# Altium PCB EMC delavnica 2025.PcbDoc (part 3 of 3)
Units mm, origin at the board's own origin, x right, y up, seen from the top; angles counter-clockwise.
Board outline 146.35 x 55.01 mm, 2 copper layers (Top Layer, Bottom Layer), stack 1.671 mm thick; 5 components, 5 nets, 32 pads, 0 vias.
Unrouted connection lines stored in the file: 7.
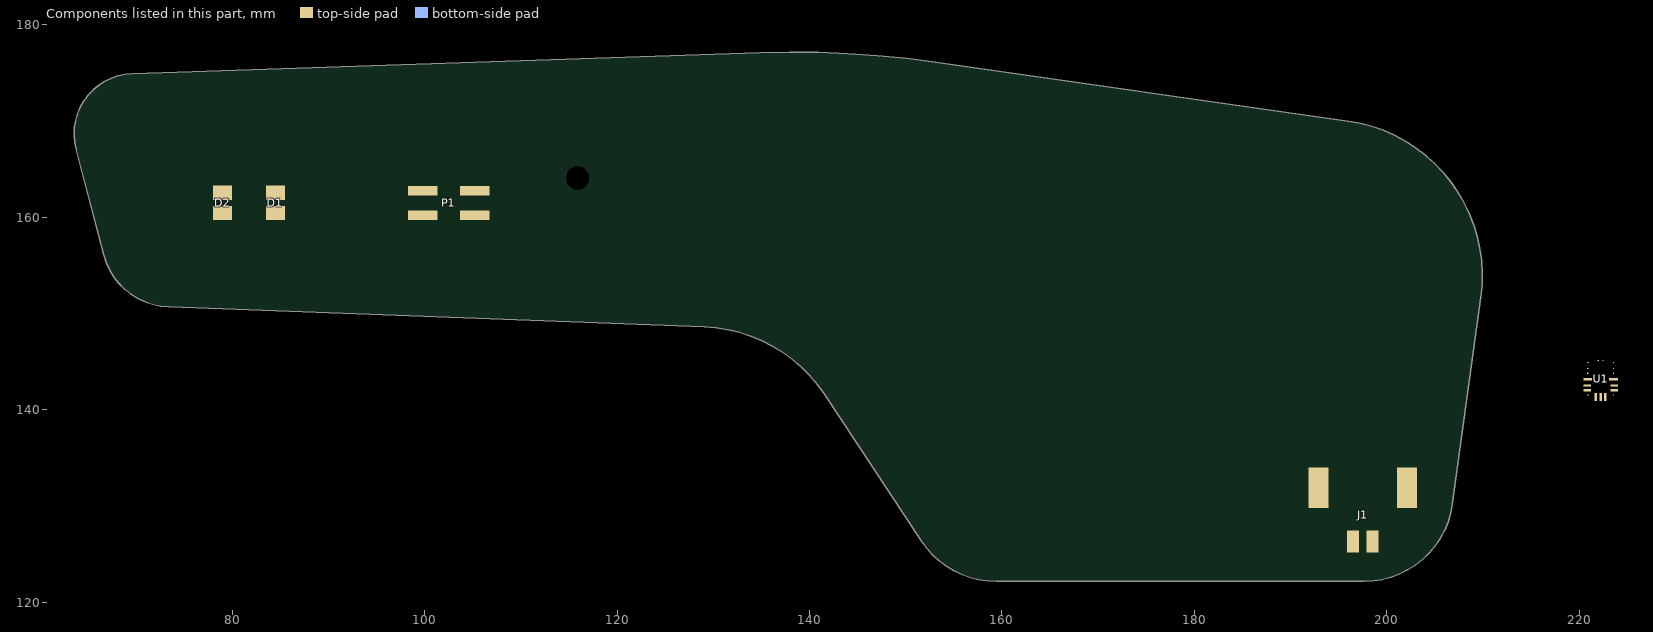
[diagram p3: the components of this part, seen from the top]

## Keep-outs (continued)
Top Layer: (continued)
  lines w0.203: 197.064,156.203 ccw(c197.307,156.588) 197.064,156.203 ; 197.064,156.203 ccw(c197.308,156.587) 197.064,156.203 ; 197.064,156.203 ccw(c197.308,156.587) 197.064,156.203 ; 197.064,156.203 ccw(c197.552,156.972) 197.064,156.203 ; 197.064,156.203 197.064,156.203 ; 197.064,156.203 ccw(c197.307,156.588) 197.064,156.203 ; 197.064,156.203 ccw(c197.308,156.587) 197.065,156.203 ; 197.064,156.203 ccw(c197.308,156.587) 197.064,156.203 ; 197.065,156.203 ccw(c197.552,156.972) 197.224,156.122 ; 197.064,156.203 ccw(c197.552,156.972) 197.224,156.122 ; 197.128,159.92 ccw(c197.499,159.088) 197.128,159.92 ; 197.128,159.92 cw(c197.499,159.088) 197.129,159.92 ; 197.128,159.92 cw(c197.314,159.504) 197.129,159.92 ; 197.128,159.92 cw(c197.313,159.504) 197.129,159.92 ; 197.128,159.92 197.129,159.92 ; 197.129,159.921 ccw(c197.313,159.504) 197.129,159.92 ; 197.129,159.921 ccw(c197.314,159.504) 197.129,159.92 ; 197.129,159.92 ccw(c197.499,159.088) 197.129,159.92 ; 197.129,159.921 ccw(c197.314,159.504) 197.129,159.92 ; 197.13,159.921 ccw(c197.314,159.504) 197.129,159.921 ; 197.13,159.921 ccw(c197.499,159.088) 197.129,159.92 ; 197.129,159.921 197.342,160.015 ; 197.129,159.92 197.129,159.921 ; 197.224,156.122 197.443,156.038 ; 197.342,160.015 ccw(c197.528,159.599) 197.341,160.015 ; 197.342,160.015 cw(c197.528,159.599) 197.342,160.015 ; 197.341,160.015 ccw(c197.713,159.183) 197.341,160.015 ; 197.342,160.015 cw(c197.527,159.599) 197.342,160.015 ; 197.341,160.015 cw(c197.713,159.183) 197.342,160.015 ; 197.341,160.015 197.342,160.015 ; 197.342,160.015 197.342,160.015 ; 197.342,160.015 197.342,160.015 ; 197.342,160.015 197.342,160.015 ; 197.342,160.015 cw(c197.528,159.599) 197.343,160.016 cw(c197.713,159.183) 197.513,160.072 ; 197.342,160.015 cw(c197.713,159.183) 197.512,160.072 ; 197.443,156.038 ccw(c197.771,156.888) 197.615,155.99 ; 197.443,156.038 ccw(c197.771,156.888) 197.615,155.99 ; 197.513,160.072 ccw(c197.713,159.183) 197.513,160.072 ; 197.513,160.072 ccw(c197.613,159.628) 197.513,160.072 ; 197.513,160.072 ccw(c197.613,159.628) 197.513,160.072 ; 197.513,160.072 cw(c197.713,159.183) 197.514,160.072 ; 197.513,160.072 cw(c197.614,159.628) 197.514,160.072 ; 197.513,160.072 ccw(c197.613,159.628) 197.512,160.072 ; 197.513,160.072 ccw(c197.614,159.628) 197.513,160.072 ; 197.513,160.072 ccw(c197.613,159.628) 197.513,160.072 ; 197.513,160.072 ccw(c197.614,159.628) 197.513,160.072 ; 197.513,160.072 197.514,160.072 ; 197.513,160.072 197.513,160.072 ; 197.513,160.072 197.513,160.072 ; 197.514,160.072 197.74,160.123 ; 197.615,155.99 ccw(c197.771,156.888) 197.615,155.99 ; 197.615,155.99 ccw(c197.694,156.439) 197.615,155.99 ; 197.615,155.99 ccw(c197.771,156.888) 197.615,155.99 ; 197.615,155.99 197.615,155.99 ; 197.615,155.99 ccw(c197.693,156.439) 197.616,155.99 ; 197.615,155.99 ccw(c197.694,156.439) 197.616,155.99 ; 197.615,155.99 ccw(c197.694,156.439) 197.617,155.99 ; 197.615,155.99 ccw(c197.771,156.888) 197.615,155.99 ; 197.616,155.99 ccw(c197.771,156.888) 197.617,155.99 ; 197.615,155.99 ccw(c197.771,156.888) 197.616,155.99 ; 197.616,155.99 197.617,155.99 ; 197.616,155.99 197.616,155.99 ; 197.617,155.99 ccw(c197.694,156.439) 197.617,155.99 ; 197.617,155.99 ccw(c197.694,156.439) 197.617,155.99 ; 197.617,155.99 197.846,155.95 ; 197.74,160.123 cw(c197.943,159.235) 197.741,160.124 ; 197.74,160.123 cw(c197.841,159.679) 197.741,160.124 ; 197.74,160.123 197.74,160.123 ; 197.74,160.123 197.741,160.124 ; 197.741,160.124 ccw(c197.842,159.679) 197.741,160.124 ; 197.742,160.124 ccw(c197.842,159.679) 197.741,160.124 ; 197.741,160.124 ccw(c197.841,159.679) 197.741,160.124 ; 197.742,160.124 ccw(c197.943,159.235) 197.741,160.124 ; 197.742,160.124 ccw(c197.841,159.679) 197.741,160.124 ; 197.742,160.124 cw(c197.943,159.235) 197.919,160.146 ; 197.742,160.124 cw(c197.943,159.235) 197.919,160.146 ; 197.741,160.124 197.742,160.124 ; 197.741,160.124 197.741,160.124 ; 197.846,155.95 ccw(c197.924,156.399) 197.846,155.95 ; 197.846,155.95 ccw(c198.003,156.848) 197.847,155.95 ; 197.846,155.95 ccw(c197.924,156.399) 197.846,155.95 ; 197.846,155.95 ccw(c198.003,156.848) 197.846,155.95 ; 197.846,155.95 ccw(c197.925,156.399) 197.847,155.95 ; 197.846,155.95 ccw(c197.925,156.399) 197.846,155.95 ; 197.846,155.95 197.846,155.95 ; 197.846,155.95 197.846,155.95 ; 197.846,155.95 197.847,155.95 ; 197.847,155.95 ccw(c198.003,156.848) 197.937,155.939 ; 197.847,155.95 ccw(c197.925,156.399) 197.847,155.95 ; 197.847,155.95 ccw(c198.003,156.848) 197.937,155.939 ; 197.846,155.95 ccw(c197.924,156.399) 197.847,155.95 ; 197.92,160.146 ccw(c197.931,159.691) 197.919,160.146 ; 197.92,160.146 ccw(c197.931,159.69) 197.919,160.146 ; 197.919,160.146 cw(c197.943,159.235) 197.92,160.146 ; 197.92,160.146 cw(c197.931,159.69) 197.92,160.146 ; 197.919,160.146 ccw(c197.931,159.69) 197.919,160.146 ; 197.92,160.146 197.92,160.146 ; 197.92,160.146 197.92,160.146 ; 197.919,160.146 197.92,160.146 ; 197.92,160.146 197.92,160.146 ; 197.92,160.146 197.92,160.146 ; 197.92,160.146 ccw(c197.943,159.235) 197.92,160.146 ; 197.92,160.146 ccw(c197.931,159.691) 197.92,160.146 ; 197.92,160.146 198.152,160.152 ; 197.937,155.939 198.734,155.881 ; 198.152,160.152 ccw(c198.165,159.697) 198.152,160.152 ; 198.152,160.152 cw(c198.165,159.697) 198.153,160.152 ; 198.152,160.152 cw(c198.178,159.241) 198.153,160.152 ; 198.152,160.152 198.153,160.152 ; 198.153,160.152 cw(c198.166,159.697) 198.154,160.152 ; 198.153,160.152 cw(c198.178,159.241) 198.154,160.152 ; 198.153,160.152 ccw(c198.165,159.697) 198.153,160.152 ; 198.153,160.152 cw(c198.165,159.697) 198.154,160.152 ; 198.153,160.152 ccw(c198.166,159.697) 198.153,160.152 ; 198.153,160.152 ccw(c198.178,159.241) 198.153,160.152 ; 198.153,160.152 198.153,160.152 ; 198.153,160.152 198.154,160.152 ; 198.154,160.152 cw(c198.178,159.241) 198.244,160.15 ; 198.154,160.152 ccw(c198.178,159.241) 198.154,160.152 ; 198.154,160.152 cw(c198.178,159.241) 198.244,160.15 ; 198.244,160.15 199.042,160.092 ; 198.734,155.881 ccw(c198.801,156.789) 198.825,155.878 ; 198.734,155.881 ccw(c198.801,156.789) 198.825,155.878 ; 198.825,155.878 ccw(c198.814,156.334) 198.826,155.878 ; 198.825,155.878 ccw(c198.814,156.334) 198.825,155.878 ; 198.825,155.878 ccw(c198.813,156.334) 198.826,155.878 ; 198.825,155.878 ccw(c198.813,156.334) 198.825,155.878 ; 198.825,155.878 ccw(c198.801,156.789) 198.826,155.878 ; 198.825,155.878 198.826,155.878 ; 198.826,155.878 ccw(c198.814,156.334) 198.827,155.878 ; 198.826,155.878 ccw(c198.801,156.789) 198.827,155.878 ; 198.826,155.878 198.827,155.878 ; 198.826,155.878 198.826,155.878 ; 198.827,155.878 199.058,155.885 ; 198.827,155.878 198.827,155.878 ; 199.042,160.092 cw(c198.976,159.183) 199.131,160.081 ; 199.042,160.092 cw(c198.976,159.183) 199.131,160.081 ; 199.058,155.885 ccw(c199.047,156.34) 199.059,155.885 ; 199.058,155.885 ccw(c199.036,156.795) 199.059,155.885 ; 199.058,155.885 ccw(c199.036,156.795) 199.058,155.885 ; 199.058,155.885 199.059,155.885 ; 199.058,155.885 199.058,155.885 ; 199.059,155.885 ccw(c199.036,156.795) 199.06,155.885 ; 199.059,155.885 ccw(c199.047,156.34) 199.06,155.885 ; 199.059,155.885 ccw(c199.048,156.34) 199.06,155.885 ; 199.059,155.885 ccw(c199.047,156.34) 199.059,155.885 ; 199.059,155.885 ccw(c199.048,156.34) 199.059,155.885 ; 199.059,155.885 ccw(c199.047,156.34) 199.059,155.885 ; 199.059,155.885 199.06,155.885 ; 199.059,155.885 199.059,155.885 ; 199.06,155.885 ccw(c199.036,156.795) 199.237,155.907 ; 199.06,155.885 ccw(c199.036,156.795) 199.237,155.907 ; 199.06,155.885 ccw(c199.036,156.795) 199.06,155.885 ; 199.131,160.081 199.363,160.04 ; 199.237,155.907 199.466,155.959 ; 199.363,160.04 cw(c199.207,159.143) 199.535,159.993 ; 199.363,160.04 cw(c199.207,159.143) 199.535,159.993 ; 199.466,155.959 ccw(c199.265,156.847) 199.635,156.015 ; 199.466,155.959 ccw(c199.265,156.847) 199.635,156.015 ; 199.535,159.993 cw(c199.207,159.143) 199.536,159.993 ; 199.535,159.993 ccw(c199.207,159.143) 199.535,159.993 ; 199.535,159.993 cw(c199.372,159.567) 199.536,159.993 ; 199.535,159.993 cw(c199.371,159.568) 199.536,159.993 ; 199.535,159.993 199.536,159.993 ; 199.537,159.992 ccw(c199.207,159.143) 199.536,159.993 ; 199.536,159.992 ccw(c199.372,159.567) 199.536,159.993 ; 199.537,159.992 cw(c199.207,159.143) 199.537,159.992 ccw(c199.372,159.567) 199.537,159.992 ; 199.537,159.992 ccw(c199.372,159.567) 199.536,159.993 ; 199.536,159.992 199.537,159.992 ; 199.537,159.992 199.753,159.909 ; 199.537,159.992 199.537,159.992 ; 199.636,156.015 ccw(c199.451,156.431) 199.636,156.015 ; 199.635,156.015 ccw(c199.265,156.847) 199.636,156.015 ; 199.636,156.015 ccw(c199.451,156.431) 199.636,156.015 ; 199.636,156.015 ccw(c199.45,156.431) 199.636,156.015 ; 199.635,156.015 ccw(c199.451,156.431) 199.636,156.015 ; 199.636,156.015 ccw(c199.265,156.847) 199.636,156.015 ; 199.635,156.015 ccw(c199.265,156.847) 199.636,156.015 ; 199.635,156.015 199.636,156.015 ; 199.636,156.015 ccw(c199.265,156.847) 199.637,156.015 ; 199.636,156.015 ccw(c199.451,156.431) 199.637,156.015 ; 199.636,156.015 199.85,156.11 ; 199.753,159.909 ccw(c199.589,159.484) 199.753,159.909 ; 199.753,159.909 cw(c199.59,159.483) 199.754,159.908 ; 199.753,159.909 cw(c199.589,159.484) 199.754,159.908 ; 199.753,159.909 ccw(c199.426,159.058) 199.753,159.909 ; 199.753,159.909 cw(c199.426,159.058) 199.754,159.908 ; 199.753,159.909 199.754,159.908 ; 199.753,159.909 199.753,159.909 ; 199.753,159.909 199.753,159.909 ; 199.754,159.908 ccw(c199.59,159.483) 199.754,159.908 ; 199.754,159.908 cw(c199.426,159.058) 199.914,159.828 ; 199.754,159.908 cw(c199.426,159.058) 199.914,159.828 ; 199.85,156.11 ccw(c199.665,156.526) 199.85,156.11 ; 199.85,156.11 ccw(c199.48,156.943) 199.85,156.11 ; 199.849,156.11 ccw(c199.665,156.526) 199.85,156.11 ; 199.849,156.11 ccw(c199.48,156.943) 199.85,156.11 ; 199.85,156.11 ccw(c199.665,156.526) 199.851,156.111 ; 199.85,156.11 ccw(c199.665,156.526) 199.85,156.11 ; 199.85,156.11 ccw(c199.665,156.527) 199.85,156.11 ccw(c199.48,156.943) 199.851,156.111 ; 199.85,156.11 ccw(c199.665,156.527) 199.85,156.11 ; 199.85,156.11 ccw(c199.48,156.943) 199.851,156.111 ; 199.85,156.11 199.851,156.111 ; 199.851,156.111 ccw(c199.48,156.943) 200.006,156.199 ; 199.851,156.111 ccw(c199.48,156.943) 200.006,156.199 ; 199.914,159.828 200.113,159.702 ; 200.006,156.199 200.198,156.334 ; 200.113,159.702 cw(c199.625,158.932) 200.253,159.592 ; 200.113,159.702 cw(c199.625,158.932) 200.253,159.592 ; 200.198,156.334 ccw(c199.672,157.079) 200.332,156.451 ; 200.198,156.334 ccw(c199.672,157.079) 200.332,156.451 ; 200.253,159.592 200.424,159.43 ; 200.332,156.451 ccw(c199.672,157.079) 200.333,156.451 ; 200.332,156.451 ccw(c200.003,156.766) 200.333,156.452 ; 200.333,156.451 ccw(c200.002,156.765) 200.333,156.452 ; 200.332,156.451 ccw(c199.672,157.079) 200.333,156.452 ; 200.332,156.451 200.333,156.452 ; 200.333,156.452 ccw(c200.003,156.766) 200.333,156.452 ; 200.333,156.452 ccw(c200.003,156.766) 200.334,156.453 ; 200.333,156.452 ccw(c199.672,157.079) 200.334,156.452 ; 200.333,156.452 200.334,156.452 ; 200.334,156.452 ccw(c199.672,157.079) 200.334,156.453 ; 200.334,156.453 200.493,156.62 ; 200.334,156.452 200.334,156.453 ; 200.424,159.43 cw(c199.795,158.77) 200.54,159.295 ; 200.424,159.43 cw(c199.795,158.77) 200.54,159.295 ; 200.493,156.62 ccw(c199.834,157.249) 200.493,156.62 ; 200.494,156.621 ccw(c200.163,156.934) 200.494,156.621 ; 200.493,156.62 ccw(c200.163,156.934) 200.494,156.621 ; 200.493,156.62 ccw(c199.834,157.249) 200.494,156.621 ; 200.493,156.62 200.494,156.621 ; 200.493,156.62 200.493,156.62 ; 200.494,156.621 ccw(c200.163,156.934) 200.494,156.621 ; 200.494,156.621 ccw(c200.164,156.935) 200.494,156.621 ; 200.494,156.621 ccw(c199.834,157.249) 200.495,156.622 ; 200.494,156.621 200.495,156.622 ; 200.494,156.621 ccw(c200.164,156.935) 200.495,156.621 ; 200.495,156.622 ccw(c199.834,157.249) 200.604,156.762 ; 200.495,156.622 ccw(c199.834,157.249) 200.604,156.762 ; 200.495,156.621 ccw(c199.834,157.249) 200.495,156.622 ; 200.494,156.621 ccw(c200.163,156.934) 200.495,156.622 ; 200.541,159.295 ccw(c200.168,159.032) 200.54,159.295 ; 200.54,159.295 ccw(c199.795,158.77) 200.54,159.295 ; 200.541,159.295 ccw(c200.168,159.032) 200.541,159.295 ; 200.541,159.295 ccw(c200.168,159.033) 200.54,159.295 ; 200.541,159.294 ccw(c200.168,159.032) 200.541,159.295 ; 200.541,159.295 ccw(c199.795,158.77) 200.54,159.295 ; 200.541,159.294 ccw(c199.795,158.77) 200.541,159.295 ; 200.541,159.294 ccw(c199.795,158.77) 200.541,159.294 ; 200.541,159.294 200.541,159.294 ; 200.54,159.295 200.541,159.295 ; 200.541,159.294 200.675,159.104 ; 200.541,159.295 200.541,159.295 ; 200.541,159.295 200.541,159.294 ; 200.604,156.762 200.73,156.961 ; 200.676,159.103 ccw(c200.303,158.841) 200.675,159.104 ; 200.676,159.103 cw(c200.303,158.841) 200.676,159.103 ; 200.675,159.103 ccw(c199.931,158.578) 200.675,159.104 ; 200.676,159.103 ccw(c199.931,158.578) 200.675,159.103 ; 200.676,159.103 ccw(c200.303,158.841) 200.675,159.104 ; 200.676,159.103 cw(c199.931,158.578) 200.676,159.103 ; 200.676,159.103 ccw(c200.303,158.841) 200.676,159.103 ; 200.676,159.103 ccw(c200.303,158.841) 200.675,159.104 ; 200.676,159.103 cw(c199.931,158.578) 200.676,159.103 ; 200.675,159.104 200.675,159.104 ; 200.675,159.104 200.675,159.103 ; 200.676,159.103 200.676,159.103 ; 200.676,159.103 cw(c199.931,158.578) 200.764,158.948 ; 200.676,159.103 cw(c199.931,158.578) 200.764,158.948 ; 200.73,156.961 ccw(c199.959,157.448) 200.81,157.121 ; 200.73,156.961 ccw(c199.959,157.448) 200.81,157.121 ; 200.764,158.948 200.859,158.733 ; 200.81,157.121 ccw(c200.385,157.285) 200.81,157.121 ; 200.81,157.121 ccw(c199.959,157.448) 200.81,157.121 ; 200.81,157.121 ccw(c200.385,157.284) 200.81,157.121 ; 200.81,157.121 ccw(c200.385,157.284) 200.81,157.121 ; 200.81,157.121 200.81,157.121 ; 200.81,157.121 ccw(c200.385,157.284) 200.81,157.121 ; 200.81,157.121 ccw(c199.959,157.448) 200.81,157.122 ; 200.81,157.121 ccw(c199.959,157.448) 200.81,157.121 ; 200.81,157.121 200.894,157.339 ; 200.859,158.733 cw(c200.026,158.363) 200.915,158.563 ; 200.859,158.733 cw(c200.026,158.363) 200.915,158.563 ; 200.894,157.339 ccw(c200.469,157.503) 200.894,157.34 ; 200.894,157.339 ccw(c200.044,157.667) 200.942,157.512 ; 200.894,157.339 ccw(c200.469,157.504) 200.894,157.34 ccw(c200.044,157.667) 200.942,157.512 ; 200.894,157.339 ccw(c200.044,157.667) 200.894,157.339 ; 200.894,157.339 ccw(c200.469,157.504) 200.894,157.339 ; 200.894,157.339 ccw(c200.044,157.667) 200.894,157.339 ; 200.894,157.339 ccw(c200.469,157.504) 200.894,157.339 ; 200.894,157.339 ccw(c200.044,157.667) 200.894,157.339 ; 200.894,157.339 200.894,157.339 ; 200.894,157.339 200.894,157.339 ; 200.915,158.563 200.967,158.334 ; 200.942,157.512 200.982,157.744 ; 200.967,158.334 cw(c200.078,158.134) 200.989,158.157 ; 200.967,158.334 cw(c200.078,158.134) 200.989,158.157 ; 200.982,157.744 ccw(c200.084,157.899) 200.995,157.899 ; 200.982,157.744 ccw(c200.084,157.899) 200.995,157.899 ; 200.989,158.157 200.995,157.922 ; 200.995,157.899 ccw(c200.084,157.899) 200.995,157.922 ; 200.995,157.899 ccw(c200.084,157.899) 200.995,157.922
Bottom Layer:
  lines w0.2: 160.031,148.63 160.075,133.289 160.118,132.655 160.242,132.033 160.475,131.363 160.809,130.715 161.244,130.094 161.781,129.506 162.42,128.958 163.157,128.462 163.988,128.024 164.905,127.657 165.899,127.367 166.958,127.165 167.867,127.069 168.79,127.038 182.587,127.077 184.089,127.123 185.568,127.252 186.744,127.42 188.069,127.686 189.3,128.018 190.423,128.405 191.426,128.839 192.305,129.308 193.058,129.801 193.685,130.308 194.19,130.819 194.579,131.325 194.861,131.822 195.047,132.309 195.137,132.724 195.166,133.141 195.121,148.977 195.079,149.463 194.953,149.947 194.737,150.436 194.384,150.984 193.904,151.536 193.29,152.082 192.537,152.613 191.643,153.117 190.61,153.584 189.44,154.001 188.141,154.357 186.726,154.64 185.21,154.84 183.867,154.939 182.508,154.969 168.711,154.93 167.68,154.886 166.667,154.759 165.707,154.555 164.801,154.28 163.96,153.938 163.191,153.537 162.502,153.086 161.896,152.592 161.376,152.063 160.942,151.507 160.595,150.928 160.332,150.332 160.151,149.72 160.06,149.18 160.031,148.63

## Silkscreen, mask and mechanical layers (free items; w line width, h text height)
Top Solder:
  drawing of 12562 lines, arcs and shapes, not listed
Board Shape:
  drawing of 296 lines, arcs and shapes, not listed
